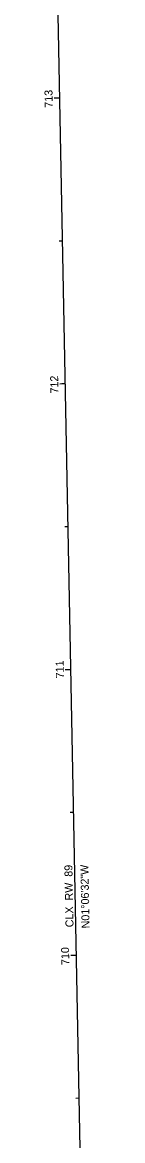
# Model space of a CAD drawing. Extents: x 2045805 to 2050091, y 455249 to 458900.
# Drawn here: x 2047611.4 to 2047631.2, y 457369.4 to 457760.7 of the extents above; entities that cross this region are included whole.
import ezdxf

# ---------------------------------------------------------------- set-up
doc = ezdxf.new("R2010")
doc.units = 0
for name, color, linetype in [('GE_P_Alignment_100_Cardinal_Points', 7, 'Continuous'), ('GE_P_Alignment_100_Curve_Data', 7, 'Continuous'), ('GE_P_Alignment_100_Stations', 7, 'Continuous'), ('GE_P_Driveway_CL', 7, 'Continuous'), ('PF_X_Ground_Line', 7, 'Continuous'), ('PV_P_EOP', 7, 'Continuous'), ('PV_X_EOP', 7, 'Continuous'), ('RW_X_CL_100_Stations', 7, 'Continuous'), ('SC_Scratch1', 7, 'Continuous'), ('SC_Scratch3', 7, 'Continuous')]:
    doc.layers.add(name, color=color, linetype=linetype)

msp = doc.modelspace()

# ---------------------------------------------------------------- linework, layer by layer
at = {"layer": 'GE_P_Alignment_100_Cardinal_Points'}
for p, q in [((2047616.87, 457734.14), (2047614.87, 457734.1)), ((2047617.84, 457684.15), (2047616.64, 457684.13)), ((2047618.8, 457634.16), (2047616.8, 457634.12)), ((2047619.77, 457584.17), (2047618.57, 457584.15)), ((2047620.74, 457534.18), (2047618.74, 457534.14)), ((2047621.71, 457484.19), (2047620.51, 457484.17)), ((2047622.67, 457434.2), (2047620.67, 457434.16)), ((2047623.64, 457384.21), (2047622.44, 457384.19))]:
    msp.add_line(p, q, dxfattribs=at)
at = {"layer": 'GE_P_Alignment_100_Stations'}
for p, q in [((2047616.87, 457734.14), (2047615.67, 457734.12)), ((2047618.8, 457634.16), (2047617.6, 457634.14)), ((2047620.74, 457534.18), (2047619.54, 457534.16)), ((2047622.67, 457434.2), (2047620.67, 457434.16))]:
    msp.add_line(p, q, dxfattribs=at)
at = {"layer": 'PV_P_EOP'}
msp.add_line((2047631.15, 456996.2), (2047613.37, 457914.72), dxfattribs=at)
at = {"layer": 'PV_X_EOP'}
msp.add_line((2047622.67, 457434.2), (2047620.67, 457434.16), dxfattribs=at)

# ---------------------------------------------------------------- texts
at = {"layer": 'GE_P_Alignment_100_Cardinal_Points'}
for s, p in [('713', (2047614.38, 457730.83)), ('712', (2047616.37, 457630.84)), ('711', (2047618.3, 457531.17)), ('710', (2047620.19, 457430.87))]:
    msp.add_text(s, height=2.8, rotation=91.1089, dxfattribs=at).set_placement(p)
at = {"layer": 'GE_P_Alignment_100_Curve_Data'}
msp.add_text('N01°06\'32"W', height=2.8, rotation=91.1089, dxfattribs=at).set_placement((2047627.29, 457443.69))
at = {"layer": 'GE_P_Alignment_100_Stations'}
msp.add_text('710', height=2.8, rotation=91.1089, dxfattribs=at).set_placement((2047620.19, 457430.87))
at = {"layer": 'GE_P_Driveway_CL'}
msp.add_text('CLX_RW_89', height=2.8, rotation=91.1089, dxfattribs=at).set_placement((2047621.66, 457444.08))
at = {"layer": 'PF_X_Ground_Line'}
msp.add_text('N01°06\'32"W', height=2.8, rotation=91.1089, dxfattribs=at).set_placement((2047627.29, 457443.69))
at = {"layer": 'PV_X_EOP'}
msp.add_text('710', height=2.8, rotation=91.1089, dxfattribs=at).set_placement((2047620.19, 457430.87))
at = {"layer": 'RW_X_CL_100_Stations'}
msp.add_text('CLX_RW_89', height=2.8, rotation=91.1089, dxfattribs=at).set_placement((2047621.66, 457444.08))
at = {"layer": 'SC_Scratch1'}
msp.add_text('N01°06\'32"W', height=2.8, rotation=91.1089, dxfattribs=at).set_placement((2047627.29, 457443.69))
at = {"layer": 'SC_Scratch3'}
msp.add_text('CLX_RW_89', height=2.8, rotation=91.1089, dxfattribs=at).set_placement((2047621.66, 457444.08))

doc.saveas('drawing.dxf')
